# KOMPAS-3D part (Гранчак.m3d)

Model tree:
1. Эскиз:1
2. Операция выдавливания:1
     Расстояние 1 = 70; Угол 1 = 4
3. Эскиз:2
4. Вырезать элемент выдавливания:1
     Расстояние 1 = 65; Угол 1 = 4
5. Эскиз:3
6. Вырезать элемент выдавливания:2
     Толщина стенки 2 = 2; Расстояние 1 = 75; Угол 1 = 4
7. Скругление:1
     Радиус = 5
8. Эскиз:4
9. Операция выдавливания:3
     Расстояние 1 = 10; Расстояние 2 = 70; Угол 2 = 1
10. Скругление:2
     Радиус = 1
11. Скругление:3
     Радиус = 1
12. Смещенная плоскость:1
     Расстояние = 65
13. Эскиз:5
14. Операция выдавливания:4
     Расстояние 1 = 10; Угол 1 = 4; Расстояние 2 = 60; Угол 2 = 4
15. Скругление:4
     Радиус = 5
16. Скругление:6
     Радиус = 3

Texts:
  Made in Ukraine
